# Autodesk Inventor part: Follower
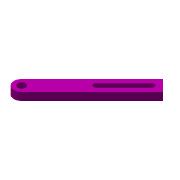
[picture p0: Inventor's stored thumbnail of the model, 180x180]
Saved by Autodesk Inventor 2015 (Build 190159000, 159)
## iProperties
Created: 2019-10
Part Number: Follower
Material: 一般
Document SubType Name: Modeling
Designer: Kuan_Lun Hsu
Density: 1 g/cm^3
Appearance: 洋紅
Mass: 604.594 g
Surface Area: 818.44 cm^2
Volume: 604.594 cm^3
Author: Kuan_Lun Hsu
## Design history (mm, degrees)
sketch "草圖1" dims "d4" = 60
  geometry: L1 (0, 220)-(200, 220); L2 (200, 220)-(200, 180); L3 (200, 180)-(0, 180); L4 (0, 180)-(0, 220); L5 (-21.213, 21.213)-(21.213, -21.213); L6 (21.213, -21.213)-(289.914, 247.487); L7 (289.914, 247.487)-(247.487, 289.914); L8 (247.487, 289.914)-(-21.213, 21.213); L9 (0, 0)-(200, 200); L10 (141.421, 141.421)-(247.487, 247.487); L11 (134.35, 148.492)-(240.416, 254.558); L12 (254.558, 240.416)-(148.492, 134.35); L13 (236.961, 152.108)-(300, 50); L14 (208.305, 143.231)-(242.687, 32.245); L15 (257.738, 173.749)-(341.553, 93.282); L16 (-60, 180)-(390, 180); L17 (390, 180)-(390, -70); L18 (390, -70)-(-60, -70); L19 (-60, -70)-(-60, 180); C1 r 10 at (200, 200); C2 r 15 at (0, 0); C3 r 30 at (300, 50); A1 r 10 centre (141.421, 141.421) between (134.35, 148.492) and (148.492, 134.35); A2 r 10 centre (247.487, 247.487) between (254.558, 240.416) and (240.416, 254.558); A3 r 60 centre (300, 50) between (242.687, 32.245) and (341.553, 93.282); A4 r 30 centre (236.961, 152.108) between (208.305, 143.231) and (257.738, 173.749); 4 further points
  constraints: 40 end point, 9 parallel, 9 tangent, 8 point on circle, 7 centre point, 4 coincident, 4 midpoint, 3 perpendicular, 2 horizontal, 2 vertical alignment, 1 collinear, 1 equal radius, 1 point on line, 5 other
  dimensions: "d0" = 40 distance between parallel lines of L3 L1; "d1" = 200 distance of L1.start L1.end; "d2" = 180 distance from line of point (0, 0) L3; "d3" = 20 diameter of C1; "d5" = 380 distance of L5.end L6.end; "d6" = 30 distance from line of L7 L10.end; "d7" = 150 distance of L11.start L11.end; "d8" = 60 diameter of A4; "d9" = 120 diameter of A3; "d10" = 120 distance of L13.start L13.end; "d11" = 300 horizontal distance of L13.end point (0, 0); "d12" = 50 vertical distance of point (0, 0) L13.end; "d13" = 60 distance between parallel lines of L19 L4; "d14" = 250 distance of L18.end L16.start; "d15" = 450 distance of L17.end L18.end; "d16" = 45 deg angle of L6 L18 (derived); "d17" = 30 diameter of C2; "d18" = 60 diameter of C3
extrude "擠出1" new body sketch "草圖1" distance "d19" = 30; taper "d20" = 0 deg
extrude "擠出2" cut sketch "草圖1" stored distance "d21" = 30; taper "d22" = 0 deg
node "工作平面1"
sketch "草圖2"
  geometry: L1 (-30, 0)-(30, 0) reference; L2 (30, 0)-(30, 30) reference; C1 r 5 at (0, 15); 4 further points
  constraints: 3 midpoint, 1 centre point, 1 coincident, 1 horizontal alignment, 1 vertical alignment
  dimensions: "d23" = 10 diameter of C1
extrude "擠出3" cut sketch "草圖2" stored distance "d24" = 10; taper "d25" = 0 deg
node "實體1"
